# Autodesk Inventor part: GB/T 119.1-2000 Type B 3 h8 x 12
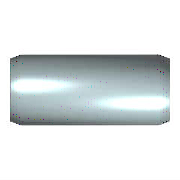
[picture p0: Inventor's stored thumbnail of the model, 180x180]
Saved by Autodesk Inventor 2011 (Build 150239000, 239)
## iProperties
Created: 2010-02
Part Number: GB/T 119.1-2000 Type B 3 h8 x 12
Material: 低炭钢
Description: B 型圆柱销
Document SubType Name: Modeling
Standard: GB/T 119.1-2000
Designer: Administrator
Standard Revision: 2000
Standards Organization: GB
Language: zh-CN
Size Designation: B 3 x 12
Categories: <MemberInstance><Categories><Category DisplayName="紧固件" InternalName="e4da775c-781d-43d5-af7c-5136215cf5a6" Mnemonic="FSTN"><Category DisplayName="销" InternalNa
Density: 1 g/cm^3
IsCustomPart: 1
Author: Administrator
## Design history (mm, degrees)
sketch "Sketch"
  geometry: C1 r 1.5 at (0, 0); 1 further point
  constraints: 1 centre point, 1 coincident
  dimensions: "d1" = 3 diameter of C1 (= NND)
extrude "Body" new body sketch "Sketch" distance "d2" = 12 (= NLG); taper "d3" = 0 deg
chamfer "Chamfer1" distance "d4" = 0.5 (= PHH); stored, may be unused: angle "d5" = 15 deg (= FAWI), second distance "d11" = 0.5 (= PHH)
chamfer "Chamfer2" distance "d8" = 0.5 (= PHH); stored, may be unused: angle "d9" = 15 deg (= FAWI), second distance "d12" = 0.5 (= PHH)
body "Solid1"
other parameters: "NND" = 3 [user parameter; used in 1 equation term], "NLG" = 12 [user parameter; used in 1 equation term], "PHH" = 0.5 [user parameter; used in 4 equation terms], "FAWI" = 15 deg [user parameter; used in 2 equation terms], "d13" = 0, "d15" = 0, "d16" = 0, "KAH" = 0 [user parameter]
